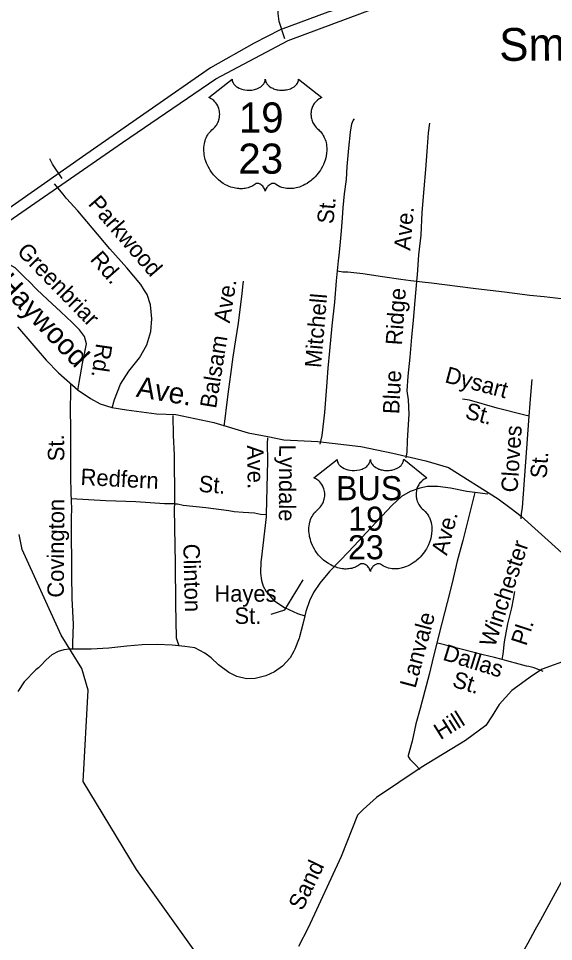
# Model space of a CAD drawing. Extents: x 925297 to 940193, y 663541 to 689899.
# Drawn here: x 927782 to 928271, y 687878 to 688722 of the extents above; entities that cross this region are included whole.
import ezdxf

# ---------------------------------------------------------------- set-up
doc = ezdxf.new("R2010")
doc.units = 0
doc.layers.add('Default', color=7, linetype='Continuous')
doc.layers.add('Old_Level_28', color=7, linetype='Continuous')

msp = doc.modelspace()

# ---------------------------------------------------------------- linework, layer by layer
at = {"layer": 'Default'}
msp.add_line((928210.79, 688287.08), (928199, 688288.68), dxfattribs=at)
for points in [[(928236.88, 688765.2), (928197.65, 688760.37), (928148.73, 688752.64), (928111.1, 688742.35), (928064.45, 688727.61), (928020.95, 688711.49), (927997.19, 688699.27), (927957.24, 688676.7), (927843.22, 688597.56), (927755.38, 688536.1), (927715.75, 688509.34), (927710.65, 688498.84)], [(927710.65, 688498.84), (927723.22, 688503.35), (927740.94, 688514.64), (927877, 688608.54), (927962.31, 688666.83), (928028.27, 688701.9), (928109.47, 688731.89), (928131.56, 688737.94), (928198.26, 688751.16), (928238.86, 688753.74)], [(928025.14, 688703.27), (928020.07, 688719.03), (928019.28, 688726.34), (928019.24, 688729.06)], [(928074.82, 688505.57), (928075.86, 688514.56), (928077.12, 688527.74), (928078.1, 688539.8), (928078.6, 688549.02), (928079.92, 688561.7), (928081.58, 688574.81), (928082.27, 688586.62), (928083.69, 688603.38), (928085.39, 688618.15), (928086.37, 688625.68), (928087.58, 688628.75), (928088.87, 688630.33)], [(928145.94, 688481.73), (928146.58, 688487.66), (928147.77, 688505.98), (928149.72, 688523.99), (928150.85, 688544.74), (928152.59, 688566.26), (928154.01, 688583.77), (928155.48, 688600.29), (928156.57, 688617.35), (928157.66, 688626.19)], [(927821.88, 688575.69), (927813, 688588.74), (927810.31, 688593.6)], [(927897.11, 688473.17), (927893.6, 688478.76), (927880.72, 688493.94), (927865.32, 688511.4), (927849, 688530.66), (927835.9, 688545.98), (927825.73, 688557.44), (927825.42, 688557.82), (927822.62, 688561.26), (927814.74, 688570.9)], [(927836.14, 688381.91), (927837.25, 688389.16), (927840.21, 688406.53), (927843.89, 688424.72), (927842.09, 688431.22), (927837.54, 688437.35), (927830.74, 688444.2), (927820.63, 688453.92), (927808.38, 688465.01), (927798.66, 688474.38), (927791.15, 688481.96), (927788.44, 688484.4), (927778.87, 688493.9), (927735.86, 688517.98)], [(928073.34, 688491.29), (928074.23, 688500.44), (928074.82, 688505.57)], [(928057.65, 688332.82), (928059.32, 688340.93), (928061.66, 688361.79), (928063.6, 688385.49), (928064.98, 688402.31), (928066.5, 688418.13), (928068.51, 688441.09), (928071.08, 688462.69), (928072.45, 688482.08), (928073.34, 688491.29)], [(928073.34, 688491.29), (928078.39, 688490.45), (928082.92, 688490.24), (928096.53, 688488.71), (928114.41, 688486.23), (928131.2, 688483.75), (928140.47, 688482.42), (928145.94, 688481.73)], [(927969.87, 688349.22), (927970.62, 688356.06), (927972.37, 688368.83), (927974.17, 688383.12), (927976, 688396.53), (927978.09, 688412.66), (927980.52, 688428.25), (927982.75, 688443.42), (927984.79, 688458.3), (927986.33, 688470.13), (927986.95, 688476.61), (927987.39, 688481.76)], [(928136.23, 688320.37), (928137.08, 688325.42), (928137.46, 688335.97), (928138.2, 688350.77), (928138.9, 688360.43), (928138.16, 688373.46), (928136.97, 688381.76), (928138.04, 688395.15), (928139.68, 688412.29), (928141.35, 688430.69), (928142.76, 688446.14), (928144.27, 688464.25), (928145.92, 688481.53), (928145.94, 688481.73)], [(928145.94, 688481.73), (928150.91, 688481.1), (928159.29, 688480.39), (928197.23, 688475.33), (928199.76, 688475.04)], [(927867.34, 688366.05), (927869.67, 688373.72), (927874.91, 688387.82), (927882.71, 688399.6), (927892.31, 688411.9), (927899.18, 688423.8), (927902.84, 688435.9), (927903.63, 688447.5), (927902.44, 688460.08), (927899.32, 688469.65), (927897.11, 688473.17)], [(928199.76, 688475.04), (928225.92, 688471.99), (928249.06, 688469.18), (928262.31, 688467.87), (928283.08, 688465.39), (928299.83, 688463.53), (928310.21, 688462.45), (928316.79, 688462.13), (928317.29, 688462.15)], [(927781, 688440.26), (927807.19, 688409.66), (927818.48, 688398.06), (927836.35, 688382.2), (927847.67, 688374.76), (927856.42, 688369.7), (927867.24, 688366.32), (927880.58, 688364.12), (927907.89, 688360.75), (927925.63, 688360.07), (927960.42, 688352.81), (927991.62, 688343.21), (928009.84, 688339.83), (928024.36, 688336.96), (928055.26, 688335.44), (928094.76, 688330.7), (928123.99, 688324.78), (928154.17, 688317.7), (928174.93, 688311.63), (928220.17, 688282.78), (928232, 688273.98), (928241.11, 688267.08), (928318.6, 688197.33)], [(928248.71, 688358.32), (928249.53, 688370.01), (928250.28, 688381.46), (928251.28, 688391.99)], [(927829.33, 688387.16), (927829.42, 688378.05), (927829.11, 688367.74), (927829.25, 688344.21), (927829.23, 688322.86), (927829.4, 688304.67), (927829.73, 688286.95), (927829.92, 688282.88)], [(928248.71, 688358.32), (928244.52, 688359.43), (928219.38, 688365.8), (928193.97, 688373.12), (928187.77, 688374)], [(927922.97, 688359), (927923.1, 688340.88), (927924.09, 688323.03), (927924.36, 688282.07), (927924.29, 688278.37)], [(928241.15, 688264.53), (928241.45, 688269.12), (928242.46, 688275.08), (928248.71, 688358.32)], [(928009.29, 688338.76), (928009.08, 688333.57), (928009.49, 688317.77), (928008.17, 688268.62)], [(928199, 688288.68), (928191.62, 688289.68), (928176.59, 688292.77), (928165.11, 688294.24), (928155.79, 688294.08), (928148.59, 688292.55), (928139.71, 688289.51), (928131.95, 688285.04), (928123.27, 688277.21), (928099.46, 688251.93), (928088.67, 688239.86), (928076.43, 688227.31), (928066.08, 688216.37), (928057.1, 688205.79), (928051.32, 688197.39), (928047.74, 688189.59), (928044.49, 688179.94), (928043.53, 688176.12)], [(928199, 688288.68), (928197.35, 688282.74), (928195.46, 688275.19), (928191.9, 688260.73), (928187.84, 688244.81), (928182.69, 688225.83), (928178.23, 688206.27), (928173.73, 688188.23), (928168.85, 688169.3), (928164.32, 688151.3), (928164.24, 688150.98)], [(927829.92, 688282.88), (927829.95, 688279.1), (927830.33, 688276.04), (927829.91, 688263.63), (927830.02, 688244.94), (927830.33, 688229.78), (927830.15, 688213.53), (927830.68, 688191.95), (927831.68, 688168.3), (927831.02, 688151.13), (927831.26, 688145.53)], [(927924.29, 688278.37), (927921.96, 688278.45), (927915.26, 688278.42), (927888.98, 688280.05), (927861.49, 688281.19), (927829.92, 688282.88)], [(927924.29, 688278.37), (927924.2, 688274.3), (927924.43, 688256.33), (927924.98, 688224.07), (927925.39, 688186.77), (927926.07, 688155.93), (927928.47, 688148.56)], [(927924.29, 688278.37), (927927.28, 688278.27), (927932.36, 688277.27), (927953, 688275.01), (927974.18, 688272.12), (927978.86, 688271.48), (927987.31, 688270.83), (927997.58, 688270.03), (928003.04, 688268.94), (928008.17, 688268.62)], [(928008.17, 688268.62), (928008.11, 688266.52), (928003.58, 688227.14), (928003.41, 688225.63), (928003.1, 688215.02), (928003.85, 688208.17), (928005.44, 688203.16), (928008.13, 688198.24), (928015.29, 688190.15), (928024.84, 688183.46), (928036.79, 688178.26), (928043.53, 688176.12)], [(928091.65, 687400.3), (928081, 687464), (928004.68, 687706.39), (927999.58, 687750.47), (927964.39, 687839.77), (927889.77, 687944.3), (927840.93, 688024.69), (927845.58, 688107.96), (927839.62, 688127.77), (927820.71, 688158.34), (927785.15, 688236.49), (927782.3, 688250.33)], [(928012.77, 688177.4), (928025.3, 688181.43), (928041.86, 688208.75)], [(928223.87, 688136.08), (928224.67, 688141.07), (928226.01, 688152.3), (928229.16, 688168.54), (928232.81, 688183.44), (928234.18, 688191.28), (928235.42, 688198.35)], [(928043.53, 688176.12), (928041.61, 688168.44), (928038.63, 688156.9)], [(928038.63, 688156.9), (928038.26, 688155.46), (928034.47, 688145.42), (928033.55, 688143.73), (928030.16, 688137.52), (928023.03, 688130.06), (928015.65, 688124.75), (928007.77, 688121.27), (927998.27, 688118.68), (927990.12, 688118.49), (927981.31, 688120.55), (927974.08, 688124.08), (927964.6, 688131.32), (927957.95, 688137.49), (927952.2, 688141.78), (927942.99, 688146.7), (927933.85, 688148.1), (927928.47, 688148.56)], [(927831.26, 688145.53), (927828.38, 688145.53), (927823.16, 688144.9), (927818.18, 688143.26), (927812.39, 688140.34), (927807.15, 688135.76), (927801.78, 688130.23)], [(927928.47, 688148.56), (927922.3, 688149.09), (927908.58, 688149.67), (927894.89, 688149.43), (927880.8, 688148.31), (927864.23, 688146.45), (927848.27, 688145.37), (927836.54, 688145.54), (927831.26, 688145.53)], [(928394.2, 688144.38), (928391.21, 688143.27), (928380.73, 688139.89), (928304.96, 688140.07), (928285.61, 688136.51), (928260.43, 688127.23), (928251.75, 688121.42), (928232.87, 688107.83), (928221.24, 688094.85), (928214.67, 688084.72), (928208.86, 688075.89), (928190.39, 688062.03), (928149.94, 688037.39), (928108.98, 688010.05), (928096.93, 687999.03), (928091.62, 687993.77), (928076.58, 687956.12), (928046.58, 687890.75), (928037.88, 687873.87)], [(928164.24, 688150.98), (928161.19, 688139.06), (928157.12, 688122.49), (928153.11, 688107.34), (928148.9, 688091.33), (928145.12, 688077.21), (928141.69, 688061.54), (928137.96, 688048.32), (928137.94, 688047.28), (928139.36, 688045.1), (928144.87, 688039.36), (928148.38, 688035.71), (928148.61, 688035.54)], [(928223.87, 688136.08), (928216.79, 688137.94), (928206.41, 688140.47), (928166.45, 688150.76), (928164.24, 688150.98)], [(928261.36, 688125.21), (928253.2, 688128.38), (928248.25, 688129.58), (928246.25, 688130.05), (928239.31, 688131.69), (928228.22, 688134.93), (928223.87, 688136.08)], [(927801.78, 688130.23), (927800.01, 688128.42), (927797.64, 688126.61), (927787.02, 688115.78), (927781.26, 688106.84)], [(928290.1, 687954.6), (928288, 687950.92), (928270.65, 687919.1), (928258.83, 687897.72), (928255.36, 687891.39)], [(928255.36, 687891.39), (928253.89, 687888.71), (928247.32, 687876.76), (928236.3, 687857.46), (928236.12, 687857.14), (928222.06, 687832), (928209.99, 687810.35), (928199.4, 687791.46), (928189.6, 687774.59), (928183.96, 687764.06), (928178.6, 687754.08), (928175.6, 687748.87)]]:
    msp.add_lwpolyline(points, dxfattribs=at)
for points in [[(927976.98, 688666.51), (927977.04, 688665.63), (927977.25, 688664.58), (927977.42, 688664.04), (927977.91, 688663.01), (927978.71, 688661.79), (927979.83, 688660.6), (927981.1, 688659.56), (927981.95, 688659.01), (927983.4, 688658.23), (927985.05, 688657.54), (927986.88, 688657.01), (927988.75, 688656.63), (927990.8, 688656.41), (927992.82, 688656.37), (927995, 688656.53), (927997.41, 688657), (927998.53, 688657.29), (927999.77, 688657.71), (928000.93, 688658.19), (928002.2, 688658.87), (928003.21, 688659.52), (928004.01, 688660.1), (928005.14, 688661.18), (928006.04, 688662.3), (928006.41, 688662.92), (928006.74, 688663.53), (928007.19, 688664.81), (928007.31, 688665.37), (928007.4, 688666.55), (928007.47, 688665.56), (928007.58, 688664.95), (928007.74, 688664.34), (928007.99, 688663.7), (928008.44, 688662.8), (928008.94, 688662.05), (928009.89, 688660.93), (928010.48, 688660.38), (928011.02, 688659.94), (928012.46, 688658.94), (928014.15, 688658.09), (928014.98, 688657.73), (928015.84, 688657.42), (928016.91, 688657.1), (928018.03, 688656.83), (928019.14, 688656.64), (928020.27, 688656.48), (928021.42, 688656.39), (928022.36, 688656.37), (928023.52, 688656.38), (928024.58, 688656.44), (928025.68, 688656.57), (928026.88, 688656.77), (928027.85, 688656.98), (928029.13, 688657.32), (928030.28, 688657.74), (928031.3, 688658.18), (928032.62, 688658.87), (928033.69, 688659.53), (928034.47, 688660.16), (928035.39, 688661.02), (928036.27, 688662.03), (928036.79, 688662.77), (928037.15, 688663.54), (928037.49, 688664.34), (928037.7, 688665.2), (928037.8, 688665.94), (928037.82, 688666.57), (928059.07, 688649.64), (928058.57, 688649.45), (928057.42, 688648.88), (928056.5, 688648.34), (928055.04, 688647.31), (928054.41, 688646.75), (928053.78, 688646.16), (928053.21, 688645.53), (928052.7, 688644.94), (928052.08, 688644.08), (928051.53, 688643.23), (928050.99, 688642.29), (928050.6, 688641.47), (928049.94, 688639.76), (928049.63, 688638.68), (928049.43, 688637.77), (928049.18, 688635.87), (928049.11, 688634.97), (928049.11, 688634.07), (928049.16, 688633.13), (928049.25, 688632.23), (928049.42, 688631.29), (928049.57, 688630.46), (928049.83, 688629.44), (928050.21, 688628.26), (928050.67, 688627.12), (928051.64, 688625.27), (928052.89, 688623.39), (928053.78, 688622.33), (928054.66, 688621.43), (928055.97, 688620.32), (928056.68, 688619.69), (928057.5, 688618.88), (928058.83, 688617.33), (928059.37, 688616.6), (928059.92, 688615.79), (928060.42, 688614.95), (928060.92, 688614.04), (928061.32, 688613.25), (928062.07, 688611.43), (928062.61, 688609.66), (928062.87, 688608.73), (928063.26, 688606.64), (928063.41, 688605.61), (928063.58, 688603.58), (928063.58, 688601.12), (928063.39, 688598.78), (928062.95, 688596.06), (928062.59, 688594.42), (928062.03, 688592.53), (928061.49, 688590.88), (928060.52, 688588.46), (928059.66, 688586.7), (928058.54, 688584.64), (928057.78, 688583.4), (928056.88, 688582.06), (928055.77, 688580.53), (928054.46, 688578.9), (928052.89, 688577.18), (928051.62, 688575.91), (928049.97, 688574.43), (928048.96, 688573.6), (928047.53, 688572.52), (928045.57, 688571.21), (928043.64, 688570.09), (928042, 688569.25), (928040.54, 688568.63), (928038.66, 688567.91), (928035.52, 688567.04), (928034.38, 688566.8), (928033.02, 688566.6), (928031.75, 688566.48), (928030.52, 688566.4), (928028.87, 688566.4), (928027.22, 688566.53), (928025.66, 688566.75), (928024.05, 688567.09), (928022.35, 688567.6), (928020.81, 688568.2), (928019.26, 688568.96), (928016.63, 688570.62), (928015.87, 688571.02), (928015.44, 688571.14), (928014.42, 688571.19), (928013.47, 688570.99), (928012.49, 688570.6), (928011.9, 688570.28), (928011.12, 688569.77), (928010.51, 688569.29), (928009.78, 688568.6), (928009.28, 688568.02), (928008.9, 688567.57), (928008.16, 688566.4), (928007.9, 688565.85), (928007.62, 688565.13), (928007.38, 688564.08), (928007.04, 688565.41), (928006.65, 688566.29), (928006.2, 688567.04), (928005.73, 688567.71), (928004.99, 688568.56), (928004.32, 688569.2), (928003.52, 688569.86), (928002.67, 688570.37), (928001.98, 688570.72), (928001.36, 688570.96), (928000.59, 688571.15), (927999.96, 688571.2), (927999.45, 688571.19), (927998.74, 688571.03), (927997.78, 688570.33), (927996.87, 688569.71), (927995.88, 688569.09), (927994.7, 688568.46), (927993.83, 688568.06), (927992.8, 688567.66), (927991.59, 688567.26), (927990.29, 688566.92), (927988.95, 688566.65), (927987.77, 688566.46), (927986.5, 688566.35), (927985.36, 688566.31), (927984.16, 688566.33), (927983.05, 688566.41), (927981.75, 688566.53), (927980.15, 688566.77), (927978.82, 688567.07), (927977.41, 688567.44), (927975.97, 688567.9), (927974.42, 688568.49), (927972.49, 688569.33), (927971.15, 688570.02), (927969.02, 688571.24), (927966.54, 688572.96), (927964.66, 688574.48), (927963.29, 688575.72), (927961.27, 688577.78), (927960.08, 688579.13), (927958.22, 688581.54), (927957.02, 688583.28), (927956.25, 688584.56), (927955.12, 688586.62), (927954.5, 688587.92), (927953.7, 688589.8), (927953.06, 688591.52), (927952.54, 688593.15), (927952.25, 688594.2), (927951.85, 688596.02), (927951.61, 688597.31), (927951.37, 688599.08), (927951.24, 688600.95), (927951.21, 688602.67), (927951.26, 688604.11), (927951.42, 688605.78), (927951.7, 688607.55), (927952.04, 688609.07), (927952.35, 688610.16), (927952.8, 688611.49), (927953.4, 688612.96), (927954.1, 688614.37), (927954.77, 688615.54), (927955.61, 688616.79), (927956.44, 688617.86), (927957.53, 688619.04), (927958.66, 688620.12), (927959.69, 688620.96), (927960.92, 688622.17), (927961.56, 688622.9), (927962.33, 688623.91), (927962.95, 688624.86), (927963.44, 688625.7), (927964.09, 688626.94), (927964.47, 688627.87), (927964.96, 688629.3), (927965.21, 688630.31), (927965.46, 688631.6), (927965.62, 688632.82), (927965.69, 688634.34), (927965.65, 688635.59), (927965.49, 688637.06), (927965.21, 688638.47), (927964.88, 688639.7), (927964.35, 688641.11), (927963.87, 688642.14), (927963.05, 688643.53), (927962.15, 688644.83), (927961.21, 688645.88), (927960.27, 688646.82), (927959.37, 688647.53), (927958.51, 688648.14), (927957.43, 688648.79), (927956.38, 688649.31), (927955.73, 688649.57)], [(928073.02, 688318.96), (928073.08, 688318.08), (928073.29, 688317.04), (928073.46, 688316.5), (928073.95, 688315.47), (928074.75, 688314.25), (928075.87, 688313.06), (928077.14, 688312.01), (928077.99, 688311.46), (928079.44, 688310.68), (928081.09, 688309.99), (928082.92, 688309.46), (928084.79, 688309.09), (928086.84, 688308.86), (928088.86, 688308.82), (928091.04, 688308.99), (928093.45, 688309.45), (928094.57, 688309.74), (928095.81, 688310.17), (928096.97, 688310.64), (928098.24, 688311.32), (928099.25, 688311.98), (928100.05, 688312.55), (928101.18, 688313.63), (928102.08, 688314.75), (928102.45, 688315.38), (928102.78, 688315.98), (928103.23, 688317.26), (928103.35, 688317.83), (928103.44, 688319), (928103.51, 688318.02), (928103.62, 688317.4), (928103.78, 688316.8), (928104.03, 688316.16), (928104.48, 688315.25), (928104.98, 688314.5), (928105.93, 688313.38), (928106.52, 688312.83), (928107.06, 688312.39), (928108.5, 688311.4), (928110.19, 688310.54), (928111.02, 688310.18), (928111.88, 688309.88), (928112.95, 688309.55), (928114.07, 688309.29), (928115.18, 688309.1), (928116.31, 688308.94), (928117.46, 688308.85), (928118.4, 688308.82), (928119.56, 688308.84), (928120.63, 688308.9), (928121.72, 688309.02), (928122.92, 688309.23), (928123.89, 688309.44), (928125.17, 688309.78), (928126.32, 688310.19), (928127.34, 688310.63), (928128.66, 688311.32), (928129.73, 688311.99), (928130.51, 688312.62), (928131.43, 688313.47), (928132.31, 688314.49), (928132.83, 688315.23), (928133.19, 688315.99), (928133.53, 688316.8), (928133.74, 688317.65), (928133.84, 688318.39), (928133.86, 688319.03), (928155.11, 688302.09), (928154.61, 688301.9), (928153.46, 688301.34), (928152.54, 688300.8), (928151.08, 688299.77), (928150.45, 688299.2), (928149.82, 688298.61), (928149.25, 688297.98), (928148.74, 688297.39), (928148.12, 688296.54), (928147.57, 688295.69), (928147.03, 688294.74), (928146.64, 688293.93), (928145.98, 688292.22), (928145.67, 688291.14), (928145.47, 688290.22), (928145.22, 688288.33), (928145.15, 688287.42), (928145.15, 688286.53), (928145.2, 688285.59), (928145.29, 688284.68), (928145.46, 688283.74), (928145.61, 688282.91), (928145.87, 688281.89), (928146.25, 688280.71), (928146.71, 688279.57), (928147.68, 688277.72), (928148.93, 688275.84), (928149.82, 688274.79), (928150.7, 688273.88), (928152.01, 688272.78), (928152.72, 688272.15), (928153.54, 688271.33), (928154.87, 688269.79), (928155.41, 688269.06), (928155.96, 688268.24), (928156.46, 688267.4), (928156.96, 688266.5), (928157.36, 688265.71), (928158.11, 688263.88), (928158.65, 688262.11), (928158.91, 688261.18), (928159.3, 688259.1), (928159.45, 688258.07), (928159.62, 688256.03), (928159.62, 688253.57), (928159.43, 688251.24), (928158.99, 688248.51), (928158.63, 688246.88), (928158.07, 688244.98), (928157.53, 688243.34), (928156.56, 688240.91), (928155.7, 688239.15), (928154.58, 688237.09), (928153.82, 688235.85), (928152.92, 688234.52), (928151.81, 688232.99), (928150.5, 688231.35), (928148.93, 688229.63), (928147.66, 688228.36), (928146.01, 688226.88), (928145, 688226.05), (928143.57, 688224.97), (928141.61, 688223.67), (928139.68, 688222.55), (928138.04, 688221.71), (928136.58, 688221.08), (928134.7, 688220.36), (928131.56, 688219.5), (928130.42, 688219.26), (928129.06, 688219.06), (928127.79, 688218.93), (928126.56, 688218.86), (928124.91, 688218.86), (928123.26, 688218.98), (928121.7, 688219.21), (928120.09, 688219.55), (928118.39, 688220.05), (928116.85, 688220.65), (928115.3, 688221.42), (928112.67, 688223.08), (928111.91, 688223.48), (928111.48, 688223.59), (928110.46, 688223.64), (928109.51, 688223.44), (928108.53, 688223.05), (928107.94, 688222.74), (928107.16, 688222.22), (928106.55, 688221.75), (928105.82, 688221.05), (928105.32, 688220.48), (928104.94, 688220.02), (928104.2, 688218.86), (928103.94, 688218.3), (928103.66, 688217.59), (928103.42, 688216.53), (928103.08, 688217.86), (928102.69, 688218.74), (928102.24, 688219.5), (928101.77, 688220.16), (928101.03, 688221.02), (928100.36, 688221.66), (928099.56, 688222.31), (928098.71, 688222.83), (928098.02, 688223.18), (928097.4, 688223.42), (928096.63, 688223.6), (928096, 688223.65), (928095.49, 688223.64), (928094.78, 688223.48), (928093.82, 688222.79), (928092.91, 688222.16), (928091.92, 688221.54), (928090.74, 688220.92), (928089.87, 688220.51), (928088.84, 688220.11), (928087.64, 688219.71), (928086.33, 688219.37), (928084.99, 688219.11), (928083.81, 688218.92), (928082.54, 688218.81), (928081.4, 688218.77), (928080.2, 688218.78), (928079.09, 688218.87), (928077.79, 688218.98), (928076.19, 688219.22), (928074.86, 688219.52), (928073.45, 688219.9), (928072.01, 688220.35), (928070.46, 688220.94), (928068.53, 688221.78), (928067.19, 688222.47), (928065.06, 688223.69), (928062.58, 688225.41), (928060.7, 688226.93), (928059.33, 688228.18), (928057.31, 688230.24), (928056.12, 688231.58), (928054.26, 688233.99), (928053.06, 688235.74), (928052.29, 688237.02), (928051.16, 688239.08), (928050.54, 688240.37), (928049.74, 688242.26), (928049.1, 688243.98), (928048.58, 688245.61), (928048.29, 688246.65), (928047.89, 688248.47), (928047.65, 688249.77), (928047.41, 688251.54), (928047.28, 688253.41), (928047.25, 688255.13), (928047.3, 688256.56), (928047.46, 688258.23), (928047.74, 688260), (928048.08, 688261.52), (928048.39, 688262.61), (928048.84, 688263.95), (928049.44, 688265.42), (928050.14, 688266.82), (928050.81, 688267.99), (928051.65, 688269.25), (928052.48, 688270.31), (928053.57, 688271.49), (928054.7, 688272.57), (928055.73, 688273.42), (928056.96, 688274.62), (928057.6, 688275.35), (928058.37, 688276.37), (928058.99, 688277.31), (928059.48, 688278.15), (928060.13, 688279.39), (928060.52, 688280.32), (928061, 688281.76), (928061.25, 688282.76), (928061.5, 688284.05), (928061.66, 688285.27), (928061.73, 688286.79), (928061.69, 688288.05), (928061.53, 688289.52), (928061.25, 688290.92), (928060.92, 688292.16), (928060.39, 688293.56), (928059.91, 688294.59), (928059.09, 688295.99), (928058.19, 688297.28), (928057.25, 688298.34), (928056.31, 688299.28), (928055.41, 688299.98), (928054.55, 688300.6), (928053.47, 688301.25), (928052.42, 688301.76), (928051.77, 688302.03)]]:
    msp.add_lwpolyline(points, close=True, dxfattribs=at)
at = {"layer": 'Old_Level_28'}
msp.add_lwpolyline([(927781, 688440.26), (927807.19, 688409.66), (927818.48, 688398.06), (927836.35, 688382.2), (927847.67, 688374.76), (927856.42, 688369.7), (927867.24, 688366.32), (927880.58, 688364.12), (927907.89, 688360.75), (927925.63, 688360.07), (927960.42, 688352.81), (927991.62, 688343.21), (928009.84, 688339.83), (928024.36, 688336.96), (928055.26, 688335.44), (928094.76, 688330.7), (928123.99, 688324.78), (928154.17, 688317.7), (928174.93, 688311.63), (928220.17, 688282.78), (928232, 688273.98), (928241.11, 688267.08), (928318.6, 688197.33)], dxfattribs=at)

# ---------------------------------------------------------------- texts
at = {"layer": 'Default'}
for s, height, rotation, p in [('Smith', 30, 0.36599, (928221.29, 688683.13)), ('Parkwood', 15, 310.83928, (927844.76, 688552.13)), ('St.', 15, 84.67548, (928069.59, 688533.72)), ('Ave.', 15, 85.06719, (928139.86, 688509.5)), ('Greenbriar', 15, 314.26439, (927779.54, 688508.1)), ('Rd.', 15, 311.23798, (927846.5, 688501.31)), ('Haywood', 19, 313.59519, (927761.36, 688478.3)), ('Ave.', 15, 80.87738, (927974.86, 688443.01)), ('Ridge', 15, 85.95525, (928132.28, 688422.92)), ('Mitchell', 15, 85.16009, (928058.31, 688402.21)), ('Balsam', 15, 80.87738, (927962.33, 688364.94)), ('Rd.', 15, 261.66056, (927852.86, 688425.54)), ('Blue', 15, 87.00526, (928129.7, 688360.06)), ('Dysart', 15, 345.08979, (928170.7, 688389.58)), ('Ave.', 19, 350.50647, (927888.71, 688376.32)), ('St.', 15, 345.08979, (928189.11, 688356.74)), ('Cloves', 15, 86.17559, (928237.82, 688288.39)), ('St.', 15, 90.85776, (927823.78, 688317.3)), ('Ave.', 15, 271.12344, (927990.63, 688331.85)), ('Lyndale', 15, 269.7228, (928020.09, 688332.54)), ('St.', 15, 86.17559, (928264.49, 688301.22)), ('Redfern', 15, 356.95163, (927838.25, 688295.71)), ('St.', 15, 355.25425, (927946.03, 688289.42)), ('Covington', 15, 89.61189, (927823.2, 688192.54)), ('Ave.', 15, 75.29666, (928173.39, 688230.58)), ('Winchester', 15, 71.84813, (928217.07, 688146.56)), ('Clinton', 15, 271.46919, (927932.39, 688241.72)), ('Lanvale', 15, 74.99728, (928144.57, 688109.12)), ('Pl.', 15, 71.84813, (928245.8, 688147.82)), ('Dallas', 15, 342.72632, (928168.77, 688135.97)), ('St.', 15, 343.17265, (928177.4, 688111.47)), ('Hill', 15, 31.91694, (928167.45, 688062.23)), ('Sand', 15, 64.21382, (928041.29, 687905.71))]:
    msp.add_text(s, height=height, rotation=rotation, dxfattribs=at).set_placement(p)
for s, height, p in [('19', 27.5, (927983.17, 688617.69)), ('23', 27.5, (927982.73, 688580.1)), ('BUS', 22, (928072.05, 688281.65)), ('19', 22, (928083.14, 688253.78)), ('23', 22, (928082.91, 688227.69)), ('Hayes', 15, (927960.84, 688188.88)), ('St.', 15, (927979.26, 688168.62))]:
    msp.add_text(s, height=height, dxfattribs=at).set_placement(p)

doc.saveas('drawing.dxf')
